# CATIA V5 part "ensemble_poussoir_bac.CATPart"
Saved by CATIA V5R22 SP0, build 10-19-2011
Part number: Poussoir_flacon
Bounding box of the stored display mesh (mm): x 27 to 187, y -64 to 112, z 0 to 48
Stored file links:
  D:\CAO_PER_MODIF_2025\CAO_PER_pick&place_2024P\Sous_Ensemble_Flacon\Verin\Poussoir_Flacon\ensemble_poussoir_bac.CATPart
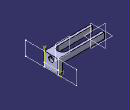
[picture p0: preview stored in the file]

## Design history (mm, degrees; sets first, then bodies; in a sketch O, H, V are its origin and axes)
Set1
  Plane1: type Offset, RefPlane face of Pocket3 from Sketch4.L1, Offset 16, reversed
Body1 (main body)
  Sketch1 on yz-plane, origin (0, 0, 0), H (0, 1, 0), V (0, 0, 1)
    line L1 (0, 0) -> (48, 0)
    line L2 (48, 0) -> (48, 48)
    line L3 (48, 48) -> (0, 48)
    line L4 (0, 48) -> (0, 0)
    point P1 (48, 0)
    point P2 (48, 48)
    point P3 (0, 48)
    distance P1 P2 = 48
    distance P2 P3 = 48
    horizontal: L1 H, L3 H
    vertical: L2 V, L4 V
  Pad1: profile Sketch1, direction (1, 0, 0), length 187
  Sketch2 on face of Pad1 from Sketch1.L4, origin (0, 0, 0), H (1, 0, 0), V (0, 0, 1)
    point P1 (15, 0)
    line L1 (15, 0) -> (173, 0)
    line L2 (173, 0) -> (173, 28)
    line L3 (173, 28) -> (15, 28)
    line L4 (15, 28) -> (15, 0)
    reference projected line E1 (0, 48) -> (187, 48) from edge [face of Pad1 from Sketch1.L4 | face of Pad1 from Sketch1.L3]
    reference projected line E2 (187, 48) -> (187, 0) from edge [face of Pad1 from Sketch1.L4 | end face of Pad1]
    reference projected line E3 (0, 48) -> (0, 0) from edge [start face of Pad1 | face of Pad1 from Sketch1.L4]
    distance L3 E1 = 20
    distance L2 E2 = 14
    distance L4 E3 = 15
    coincidence: P1 H
    horizontal: L1 H, L3 H
    vertical: L2 V, L4 V
  Pocket1: profile Sketch2, direction (0, 1, 0), through (limit type 3)
  Sketch3 on start face of Pad1, origin (0, 0, 0), H (0, -1, 0), V (0, 0, 1)
    line L1 (-41, 0) -> (-7, 0)
    line L2 (-7, 0) -> (-7, 31.5)
    line L3 (-41, 31.5) -> (-41, 0)
    point P2 (-7, 0)
    point P3 (-7, 49)
    point P4 (-41, 49)
    reference projected line E1 (0, 48) -> (0, 0) from edge [start face of Pad1 | face of Pad1 from Sketch1.L4]
    reference projected line E2 (-48, 0) -> (-48, 48) from edge [start face of Pad1 | face of Pad1 from Sketch1.L2]
    reference projected line E3 (0, 0) -> (-48, 0) from edge [start face of Pad1 | face of Pad1 from Sketch1.L1]
    point P5 (-7, 31.5)
    point P6 (-41, 31.5)
    arc A1 centre (-24, 25.5839) radius 18 from (-7, 31.5) to (-41, 31.5) ccw
    point P8 (-7, 31.5)
    point P9 (-41, 31.5)
    distance L2 E1 = 7
    distance L3 E2 = 7
    length L3 = 31.5
    radius A1 = 18
    distance P5 P2 = 31.5
    horizontal: L1 H
    vertical: L2 V, L3 V
    coincidence: E3 L1, L3 P6, L2 P5, P5 P8, P6 P9
  Pocket2: profile Sketch3, direction (1, 0, 0), up to face of Pocket1 from Sketch2.L4
  Sketch4 on face of Pad1 from Sketch1.L3, origin (0, 0, 48), H (1, 0, 0), V (0, 1, 0)
    point P1 (90, 24)
    line L1 (148, 8) -> (28, 8)
    line L2 (28, 40) -> (148, 40)
    point P3 (148, 8)
    point P4 (28, 8)
    arc A1 centre (148, 24) radius 16 from (148, 40) to (148, 8) cw
    arc A2 centre (28, 24) radius 16 from (28, 8) to (28, 40) cw
    point P7 (28, 24)
    reference projected line E1 (0, 48) -> (0, 0) from edge [start face of Pad1 | face of Pad1 from Sketch1.L3]
    distance L1 L2 = 32
    distance P3 P4 = 120
    radius A1 = 16
    radius A2 = 16
    distance P7 E1 = 28
    horizontal: L1 H, L2 H
    equidistance: L1 L2 P1
    fix: P1
  Pocket3: profile Sketch4, direction (0, 0, -1), through (limit type 3)
  Sketch5 on face of Pocket1 from Sketch2.L2, origin (173, 0, 0), H (0, 1, 0), V (0, 0, 1)
    circle A1 centre (24, 35.5) radius 4.25
    point P1 (24, 35.5)
    reference projected line E1 (48, 0) -> (48, 48) from edge [face of Pad1 from Sketch1.L2 | end face of Pad1]
    reference projected line E2 (48, 48) -> (0, 48) from Sketch7.L2
    distance P1 E1 = 24
    radius A1 = 4.25
    distance P1 E2 = 12.5
  Pocket4: profile Sketch5, direction (1, 0, 0), length 7.5, opposite side through (limit type 3)
  Sketch6 on end face of Pad1, origin (187, 0, 0), H (0, 1, 0), V (0, 0, 1)
    circle A1 centre (24, 35.5) radius 9
    point P1 (24, 35.5)
    reference projected line E1 (48, 48) -> (0, 48) from edge [face of Pad1 from Sketch1.L3 | end face of Pad1]
    radius A1 = 9
    distance E1 P1 = 12.5
  Pocket5: profile Sketch6, direction (-1, 0, 0), length 9
  Sketch7 on face of Pad1 from Sketch1.L3, origin (0, 0, 48), H (1, 0, 0), V (0, 1, 0)
    point P2 (82, 0)
    line L1 (82, 48) -> (0, 48)
    point P3 (0, 48)
    point P4 (0, 48)
    line L2 (0, 48) -> (0, 0)
    point P5 (0, 0)
    line L3 (0, 0) -> (82, 0)
    reference projected line E1 (0, 48) -> (187, 48) from edge [face of Pad1 from Sketch1.L3 | face of Pad1 from Sketch1.L2]
    reference projected line E2 (0, 48) -> (0, 0) from edge [start face of Pad1 | face of Pad1 from Sketch1.L3]
    line L4 (82, 48) -> (82, 0)
    point P6 (82, 0)
    reference projected line E3 (187, 48) -> (187, 0) from edge [face of Pad1 from Sketch1.L3 | end face of Pad1]
    distance E3 L4 = 105
    horizontal: L1 H, L3 H
    coincidence: P5 H, E1 P4, P3 P4, L2 E2, P6 L3, P6 P2
    vertical: L2 V, L4 V
  Sketch8 on face of Pad1 from Sketch1.L3, origin (0, 0, 48), H (1, 0, 0), V (0, 1, 0)
    point P1 (27, 0)
    line L1 (27, 0) -> (-18.3471, 0)
    line L2 (-18.3471, 0) -> (-18.3471, 53.3245)
    line L3 (-18.3471, 53.3245) -> (27, 53.3245)
    line L4 (27, 53.3245) -> (27, 0)
    reference projected line E1 (187, 48) -> (187, 0) from edge [face of Pad1 from Sketch1.L3 | end face of Pad1]
    distance L4 E1 = 160
    coincidence: P1 H
    horizontal: L1 H, L3 H
    vertical: L2 V, L4 V
  Pocket6: profile Sketch8, direction (0, 0, -1), through (limit type 3)
  Sketch9 on end face of Pad1, origin (187, 0, 0), H (0, 1, 0), V (0, 0, 1)
    point P1 (48, 48)
    line L1 (48, 48) -> (112, 48)
    line L2 (112, 48) -> (112, 0)
    line L3 (112, 0) -> (48, 0)
    line L4 (48, 0) -> (48, 48)
    point P2 (112, 48)
    point P3 (112, 0)
    point P4 (48, 0)
    reference projected line E1 (48, 0) -> (48, 48) from edge [face of Pad1 from Sketch1.L2 | end face of Pad1]
    reference projected line E2 (48, 48) -> (0, 48) from edge [face of Pad1 from Sketch1.L3 | end face of Pad1]
    reference intersected line E3 through (24, 0) direction (0, -1) from Plane1
    point P7 (-64, 48)
    point P8 (0, 48)
    line L5 (0, 48) -> (-64, 48)
    point P9 (-64, 0)
    line L6 (-64, 48) -> (-64, 0)
    point P10 (0, 0)
    line L7 (-64, 0) -> (0, 0)
    point P11 (0, 48)
    point P12 (0, 0)
    line L8 (0, 0) -> (0, 48)
    distance L2 L6 = 176
    horizontal: L1 H, L3 H
    vertical: L2 V, L4 V
    coincidence: P3 H, L4 E1, L1 E2
    symmetry: P2 P7 E3, P1 P8 E3, L1 L5 E3, P3 P9 E3, L2 L6 E3, P4 P10 E3, L3 L7 E3, P1 P11 E3, P4 P12 E3, L4 L8 E3
  Sketch10 on end face of Pad1, origin (187, 0, 0), H (0, 1, 0), V (0, 0, 1)
    point P1 (48, 0)
    line L1 (48, 0) -> (0, 0)
    line L2 (0, 0) -> (0, 13.702)
    line L3 (0, 13.702) -> (48, 13.702)
    line L4 (48, 13.702) -> (48, 0)
    point P3 (0, 13.702)
    reference projected line E1 (48, 0) -> (48, 48) from edge [face of Pad1 from Sketch1.L2 | end face of Pad1]
    reference projected line E2 (48, 48) -> (0, 48) from Sketch7.L2
    distance E2 L3 = 34.298
    coincidence: P1 H, P3 V, L4 E1
    horizontal: L1 H, L3 H
    vertical: L2 V, L4 V
  Pocket7: profile Sketch7, direction (0, 0, -1), length 187
Current feature: Pocket6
